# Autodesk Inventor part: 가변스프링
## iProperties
Created: 2015-01
Part Number: 가변스프링
Document SubType Name: Modeling
Designer: elite
Density: 7.87 g/cm^3
Material: 탄소강
Mass: 79.8619 g
Surface Area: 103.229 cm^2
Volume: 10.1476 cm^3
Author: elite
